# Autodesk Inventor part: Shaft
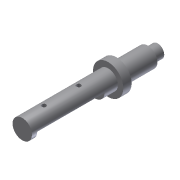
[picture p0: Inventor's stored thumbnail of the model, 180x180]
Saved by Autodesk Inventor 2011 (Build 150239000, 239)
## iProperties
Created: 2009-04
Part Number: Shaft
Document SubType Name: Modeling
Designer: Sham
Density: 1 g/cm^3
Author: Sham
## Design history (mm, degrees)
sketch "Sketch1"
  geometry: C1 r 18.75 at (511.175, 103.188)
  constraints: 1 centre point
  dimensions: "d0" = 37.5 diameter of C1
extrude "Extrusion1" new body sketch "Sketch1" distance "d1" = 28.9; taper "d2" = 0 deg
sketch "Sketch2"
  geometry: C1 r 28 at (0, 0)
  constraints: 1 centre point
  dimensions: "d3" = 56 diameter of C1
extrude "Extrusion2" join sketch "Sketch2" distance "d4" = 89.8; taper "d5" = 0 deg
sketch "Sketch3"
  geometry: C1 r 43.6 at (0, 0)
  constraints: 1 centre point
  dimensions: "d6" = 87.2 diameter of C1
extrude "Extrusion3" join sketch "Sketch3" distance "d7" = 24; taper "d8" = 0 deg
sketch "Sketch4"
  geometry: C1 r 43.6 at (0, 0) reference; C2 r 28 at (0, 0)
  constraints: 1 centre point, 1 coincident
  dimensions: "d9" = 56 diameter of C2
extrude "Extrusion4" join sketch "Sketch4" distance "d10" = 247.1; taper "d11" = 0 deg
workplane "Work Plane1"
sketch "Sketch5"
  geometry: L1 (28, 0)-(-28, 0); C1 r 43.6 at (0, 0) reference; A1 r 28 centre (0, 0) between (-28, 0) and (28, 0)
  constraints: 2 end point, 2 point on circle, 1 centre point, 1 concentric, 1 horizontal
  dimensions: "d13" = 56 diameter of A1
extrude "Extrusion5" cut sketch "Sketch5" distance "d14" = 193.8; taper "d15" = 0 deg
hole "Hole1" diameter "d18" = 12.5; stored, may be unused: countersink angle "d22" = 90 deg, drill point angle "d24" = 118 deg; dims "d16" = 28, "d17" = 46.9, "d19" = 6, "d20" = 4, "d21" = 2, "d23" = 8
pattern_linear "Rectangular Pattern1" dims "d27" = 100
body "Solid1"
other parameters: "d12" = -15.1
